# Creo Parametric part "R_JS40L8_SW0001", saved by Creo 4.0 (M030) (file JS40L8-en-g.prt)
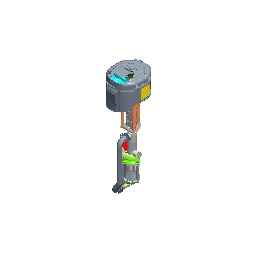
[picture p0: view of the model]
Units: Inch lbm Second (Pro/E Default); INCH, POUND, SECS

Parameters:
  COPY_GEOM_ORIGIN_TYPE = "Part"

Created from: INLBS_PART_SOLID.PRT

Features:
  1. datum plane "RIGHT"
  2. datum plane "TOP"
  3. datum plane "FRONT"
  4. coordinate system
  5. feature "Extern Copy Geom id 40"
  6. feature "Extern Copy Geom id 53"
  7. feature "Extern Copy Geom id 2621"
  8. feature "Extern Copy Geom id 4306"
  9. feature "Extern Copy Geom id 4344"
  10. feature "Extern Copy Geom id 4376"
  11. feature "Extern Copy Geom id 4439"
  12. feature "Extern Copy Geom id 4502"
  13. feature "Extern Copy Geom id 4516"
  14. feature "Extern Copy Geom id 4530"
  15. feature "Extern Copy Geom id 4544"
  16. feature "Extern Copy Geom id 4558"
  17. feature "Extern Copy Geom id 4581"
  18. feature "Extern Copy Geom id 7854"
  19. feature "Extern Copy Geom id 12271"
  20. feature "Extern Copy Geom id 12321"
  21. feature "Extern Copy Geom id 12374"
  22. feature "Extern Copy Geom id 17370"
  23. feature "Extern Copy Geom id 17420"
  24. feature "Extern Copy Geom id 17876"
  25. feature "Extern Copy Geom id 17926"
  26. feature "Extern Copy Geom id 18464"
  27. feature "Extern Copy Geom id 19069"
  28. feature "Extern Copy Geom id 19097"
  29. feature "Extern Copy Geom id 19116"
  30. feature "Extern Copy Geom id 19125"
  31. feature "Extern Copy Geom id 19134"
  32. feature "Extern Copy Geom id 19148"
  33. feature "Extern Copy Geom id 20028"
  34. feature "Extern Copy Geom id 20071"
  35. feature "Extern Copy Geom id 20185"
  36. feature "Extern Copy Geom id 20296"
  37. feature "Extern Copy Geom id 20790"
  38. feature "Extern Copy Geom id 20832"
  39. feature "Extern Copy Geom id 20845"
  40. feature "Extern Copy Geom id 20895"
  41. feature "Extern Copy Geom id 21085"
  42. feature "Extern Copy Geom id 21162"
  43. feature "Extern Copy Geom id 21239"
  44. feature "Extern Copy Geom id 21324"
  45. feature "Extern Copy Geom id 21409"
  46. feature "Extern Copy Geom id 21887"
  47. feature "Extern Copy Geom id 22800"
  48. feature "Extern Copy Geom id 22820"
  49. feature "Extern Copy Geom id 22907"
  50. feature "Extern Copy Geom id 22969"
  51. feature "Extern Copy Geom id 23016"
  52. feature "Extern Copy Geom id 23063"
  53. feature "Extern Copy Geom id 23110"
  54. feature "Extern Copy Geom id 24430"
  55. feature "Extern Copy Geom id 24962"
  56. feature "Extern Copy Geom id 26060"
  57. feature "Extern Copy Geom id 26841"
  58. feature "Extern Copy Geom id 26855"
  59. feature "Extern Copy Geom id 26869"
  60. feature "Extern Copy Geom id 26886"
  61. feature "Extern Copy Geom id 26903"
  62. feature "Extern Copy Geom id 26920"
  63. feature "Extern Copy Geom id 26976"
  64. feature "Extern Copy Geom id 27032"
  65. feature "Extern Copy Geom id 27088"
  66. feature "Extern Copy Geom id 28293"
  67. feature "Extern Copy Geom id 28373"
  68. feature "Extern Copy Geom id 28386"
  69. feature "Extern Copy Geom id 28399"
  70. feature "Extern Copy Geom id 28412"
  71. feature "Extern Copy Geom id 28425"
  72. feature "Extern Copy Geom id 28444"
  73. feature "Extern Copy Geom id 28454"
  74. feature "Extern Copy Geom id 28464"
  75. feature "Extern Copy Geom id 28471"
  76. feature "Extern Copy Geom id 28528"
  77. feature "Extern Copy Geom id 28548"
  78. feature "Extern Copy Geom id 28574"
  79. feature "Extern Copy Geom id 28627"
  80. feature "Extern Copy Geom id 28680"
  81. feature "Extern Copy Geom id 28815"
  82. feature "Extern Copy Geom id 28834"
  83. feature "Extern Copy Geom id 28853"
  84. feature "Extern Copy Geom id 28864"
  85. feature "Extern Copy Geom id 28875"
  86. feature "Extern Copy Geom id 28894"
  87. feature "Extern Copy Geom id 28913"
  88. feature "Extern Copy Geom id 28932"
  89. feature "Extern Copy Geom id 28951"
  90. feature "Extern Copy Geom id 28975"
  91. feature "Extern Copy Geom id 28999"
  92. feature "Extern Copy Geom id 29018"
  93. feature "Extern Copy Geom id 29037"
  94. feature "Extern Copy Geom id 29050"
  95. feature "Extern Copy Geom id 29063"
  96. feature "Extern Copy Geom id 29074"
  97. feature "Extern Copy Geom id 29085"
  98. feature "Extern Copy Geom id 29104"
  99. feature "Extern Copy Geom id 29123"
  100. feature "Extern Copy Geom id 29142"
  101. feature "Extern Copy Geom id 29161"
  102. feature "Extern Copy Geom id 29683"
  103. feature "Extern Copy Geom id 29697"
  104. feature "Extern Copy Geom id 30120"
  105. feature "Extern Copy Geom id 30544"
  106. feature "Extern Copy Geom id 30555"
  107. feature "Extern Copy Geom id 30618"
  108. feature "Extern Copy Geom id 30648"
  109. feature "Extern Copy Geom id 30678"
  110. feature "Extern Copy Geom id 30708"
  111. feature "Extern Copy Geom id 30738"
  112. feature "Extern Copy Geom id 30809"
  113. feature "Extern Copy Geom id 30844"
  114. feature "Extern Copy Geom id 30915"
  115. feature "Extern Copy Geom id 30951"
  116. feature "Extern Copy Geom id 30964"
  117. feature "Extern Copy Geom id 31049"
  118. feature "Extern Copy Geom id 31135"
  119. feature "Extern Copy Geom id 31220"
  120. feature "Extern Copy Geom id 31323"
  121. feature "Extern Copy Geom id 31548"
  122. feature "Extern Copy Geom id 31565"
  123. feature "Extern Copy Geom id 31582"
  124. feature "Extern Copy Geom id 32701"
  125. feature "Extern Copy Geom id 33833"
